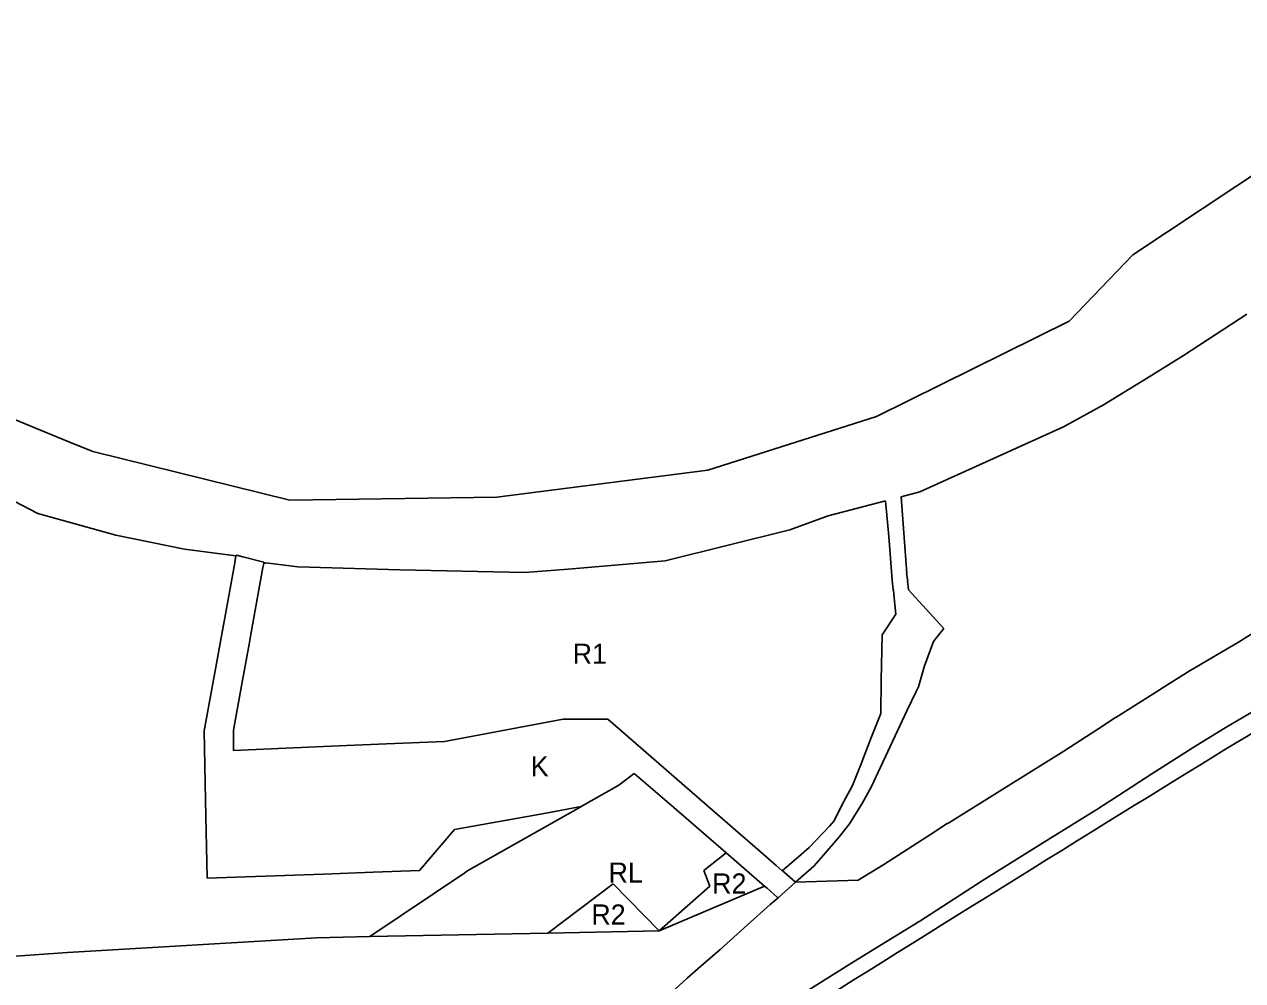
# Model space of a CAD drawing. Extents: x 7413438 to 7416393, y 5541665 to 5544118.
# Drawn here: x 7415261.6 to 7415625.7, y 5543211 to 5543496.8 of the extents above; entities that cross this region are included whole.
import ezdxf

# ---------------------------------------------------------------- set-up
doc = ezdxf.new("R2010")
doc.units = 0
for name, color, linetype in [('linie_rozgraniczajace', 7, 'Continuous'), ('linie_zabudowy_nieprzekraczalne', 7, 'Continuous'), ('oznaczenia_przeznaczen', 7, 'Continuous')]:
    doc.layers.add(name, color=color, linetype=linetype)

msp = doc.modelspace()

# ---------------------------------------------------------------- linework, layer by layer
at = {"layer": 'linie_rozgraniczajace'}
for p, q in [((7415592.88, 5543427.88), (7415696.54, 5543496.79)), ((7415573.83, 5543408.05), (7415592.88, 5543427.88)), ((7415626.92, 5543410.15), (7415608.04, 5543397.87)), ((7415516.21, 5543379.59), (7415573.83, 5543408.05)), ((7415608.04, 5543397.87), (7415596.16, 5543390.5)), ((7415231.77, 5543389.62), (7415274.89, 5543372.05)), ((7415591.51, 5543387.62), (7415584.28, 5543383.14)), ((7415596.16, 5543390.5), (7415591.51, 5543387.62)), ((7415584.28, 5543383.14), (7415572.1, 5543376.55)), ((7415465.82, 5543363.51), (7415516.21, 5543379.59)), ((7415572.1, 5543376.55), (7415529.2, 5543357.07)), ((7415274.89, 5543372.05), (7415282.08, 5543369.12)), ((7415282.08, 5543369.12), (7415340.86, 5543354.54)), ((7415402.82, 5543355.53), (7415465.82, 5543363.51)), ((7415265.57, 5543350.61), (7415253.67, 5543356.74)), ((7415340.86, 5543354.54), (7415402.82, 5543355.53)), ((7415529.2, 5543357.07), (7415523.58, 5543355.59)), ((7415523.58, 5543355.59), (7415525.28, 5543332.71)), ((7415518.92, 5543354.37), (7415501.79, 5543349.87)), ((7415519.95, 5543343.71), (7415518.92, 5543354.37)), ((7415288.87, 5543344.14), (7415265.57, 5543350.61)), ((7415501.79, 5543349.87), (7415490.31, 5543345.69)), ((7415309.43, 5543339.94), (7415288.87, 5543344.14)), ((7415490.31, 5543345.69), (7415453.09, 5543336.5)), ((7415520.89, 5543330.71), (7415519.95, 5543343.71)), ((7415324.81, 5543337.93), (7415309.43, 5543339.94)), ((7415324.48, 5543335.85), (7415324.81, 5543337.93)), ((7415324.85, 5543337.92), (7415324.81, 5543337.93)), ((7415324.9, 5543338.15), (7415324.85, 5543337.92)), ((7415325.01, 5543338.12), (7415324.9, 5543338.15)), ((7415326.84, 5543337.65), (7415325.01, 5543338.12)), ((7415333.18, 5543336.04), (7415326.84, 5543337.65)), ((7415453.09, 5543336.5), (7415424.06, 5543334)), ((7415321.07, 5543317.24), (7415324.48, 5543335.85)), ((7415332.88, 5543334.42), (7415329.35, 5543315.04)), ((7415333.13, 5543335.66), (7415332.88, 5543334.42)), ((7415333.11, 5543335.65), (7415333.18, 5543336.04)), ((7415333.13, 5543335.66), (7415333.11, 5543335.65)), ((7415333.69, 5543335.89), (7415333.13, 5543335.66)), ((7415343.27, 5543334.69), (7415333.69, 5543335.89)), ((7415373.76, 5543333.81), (7415343.27, 5543334.69)), ((7415411.13, 5543332.95), (7415373.76, 5543333.81)), ((7415424.06, 5543334), (7415411.13, 5543332.95)), ((7415525.28, 5543332.71), (7415525.23, 5543332.68)), ((7415525.23, 5543332.68), (7415525.57, 5543330.36)), ((7415520.93, 5543330.73), (7415520.89, 5543330.71)), ((7415521.22, 5543327.69), (7415520.93, 5543330.73)), ((7415525.57, 5543330.36), (7415525.52, 5543330.33)), ((7415525.52, 5543330.33), (7415525.8, 5543327.81)), ((7415521.3, 5543327.74), (7415521.22, 5543327.69)), ((7415521.42, 5543326.36), (7415521.3, 5543327.74)), ((7415522.04, 5543320.53), (7415521.42, 5543326.36)), ((7415525.8, 5543327.81), (7415536.39, 5543316.28)), ((7415517.9, 5543314.35), (7415522.04, 5543320.53)), ((7415320.37, 5543313.41), (7415320.98, 5543316.75)), ((7415320.98, 5543316.75), (7415321.03, 5543317)), ((7415321.03, 5543317), (7415321.07, 5543317.24)), ((7415329.34, 5543315), (7415328.71, 5543311.53)), ((7415329.35, 5543315.04), (7415329.34, 5543315)), ((7415536.39, 5543316.28), (7415534.33, 5543313.71)), ((7415633.26, 5543317.76), (7415624.41, 5543312.15)), ((7415318.77, 5543304.69), (7415320.37, 5543313.41)), ((7415328.71, 5543311.53), (7415326.45, 5543299.13)), ((7415517.62, 5543300.82), (7415517.9, 5543314.35)), ((7415533.3, 5543312.37), (7415530.61, 5543305.07)), ((7415534.33, 5543313.71), (7415533.3, 5543312.37)), ((7415624.41, 5543312.15), (7415610.19, 5543303.74)), ((7415315.3, 5543285.69), (7415318.77, 5543304.69)), ((7415530.61, 5543305.07), (7415528.76, 5543298.82)), ((7415610.01, 5543303.63), (7415601.1, 5543298.11)), ((7415610.19, 5543303.74), (7415610.01, 5543303.63)), ((7415517.52, 5543290.82), (7415517.62, 5543300.82)), ((7415326.45, 5543299.13), (7415324.03, 5543285.83)), ((7415528.12, 5543297.43), (7415525.36, 5543291.78)), ((7415528.76, 5543298.82), (7415528.12, 5543297.43)), ((7415601.01, 5543298.05), (7415587.77, 5543289.65)), ((7415601.02, 5543298.06), (7415601.01, 5543298.05)), ((7415601.1, 5543298.11), (7415601.02, 5543298.06)), ((7415620.46, 5543286.58), (7415634.72, 5543295.01)), ((7415387.11, 5543282.49), (7415422.61, 5543289.16)), ((7415422.61, 5543289.16), (7415435.94, 5543289.13)), ((7415435.94, 5543289.13), (7415443.47, 5543282.57)), ((7415514.58, 5543283.36), (7415517.52, 5543290.82)), ((7415525.36, 5543291.78), (7415517.47, 5543274.82)), ((7415587.68, 5543289.6), (7415582.43, 5543286.19)), ((7415587.77, 5543289.65), (7415587.68, 5543289.6)), ((7415315.74, 5543264.96), (7415315.3, 5543285.69)), ((7415324.03, 5543285.83), (7415324.1, 5543279.78)), ((7415582.43, 5543286.19), (7415572.2, 5543279.56)), ((7415611.68, 5543281.14), (7415620.46, 5543286.58)), ((7415353.24, 5543281.03), (7415369.82, 5543281.75)), ((7415369.82, 5543281.75), (7415387.11, 5543282.49)), ((7415443.47, 5543282.57), (7415465.75, 5543263.2)), ((7415511.7, 5543275.79), (7415514.58, 5543283.36)), ((7415324.1, 5543279.78), (7415353.24, 5543281.03)), ((7415572.2, 5543279.56), (7415555.59, 5543269.21)), ((7415598.52, 5543272.79), (7415611.68, 5543281.14)), ((7415509.1, 5543269.26), (7415511.7, 5543275.79)), ((7415517.47, 5543274.82), (7415514.71, 5543268.98)), ((7415443.84, 5543272.94), (7415439.21, 5543269.37)), ((7415455.65, 5543262.72), (7415443.84, 5543272.94)), ((7415586.61, 5543265.07), (7415598.52, 5543272.79)), ((7415439.21, 5543269.37), (7415427.97, 5543263)), ((7415505.78, 5543263.24), (7415509.1, 5543269.26)), ((7415514.71, 5543268.98), (7415512.05, 5543264.16)), ((7415555.59, 5543269.21), (7415537.54, 5543258)), ((7415316.24, 5543241.6), (7415315.74, 5543264.96)), ((7415512.05, 5543264.16), (7415508.17, 5543257.86)), ((7415583, 5543262.73), (7415586.61, 5543265.07)), ((7415416.96, 5543260.99), (7415390.16, 5543256.15)), ((7415427.91, 5543262.97), (7415393.84, 5543243.68)), ((7415426.36, 5543262.69), (7415416.96, 5543260.99)), ((7415427.97, 5543263), (7415426.36, 5543262.69)), ((7415427.97, 5543263), (7415427.91, 5543262.97)), ((7415471.17, 5543249.29), (7415455.65, 5543262.72)), ((7415465.75, 5543263.2), (7415481.49, 5543249.55)), ((7415503.61, 5543258.7), (7415505.78, 5543263.24)), ((7415566.16, 5543252.24), (7415582.85, 5543262.64)), ((7415582.85, 5543262.64), (7415582.91, 5543262.67)), ((7415582.91, 5543262.67), (7415583, 5543262.73)), ((7415390.16, 5543256.15), (7415379.69, 5543243.87)), ((7415496.11, 5543250.76), (7415502.15, 5543257.11)), ((7415502.15, 5543257.11), (7415503.61, 5543258.7)), ((7415508.17, 5543257.86), (7415505.14, 5543254.05)), ((7415537.39, 5543257.91), (7415532.69, 5543254.87)), ((7415537.47, 5543257.95), (7415537.39, 5543257.91)), ((7415537.54, 5543258), (7415537.47, 5543257.95)), ((7415505.14, 5543254.05), (7415499.73, 5543247.72)), ((7415532.69, 5543254.87), (7415518.44, 5543245.68)), ((7415464.62, 5543243.92), (7415471.32, 5543249.16)), ((7415471.32, 5543249.16), (7415471.17, 5543249.29)), ((7415482, 5543239.91), (7415471.32, 5543249.16)), ((7415481.49, 5543249.55), (7415486.28, 5543245.39)), ((7415492.91, 5543248.02), (7415496.11, 5543250.76)), ((7415548.17, 5543241.06), (7415566.15, 5543252.23)), ((7415566.15, 5543252.23), (7415566.16, 5543252.24)), ((7415486.28, 5543245.39), (7415488.05, 5543243.85)), ((7415488.17, 5543243.95), (7415492.91, 5543248.02)), ((7415499.73, 5543247.72), (7415497.48, 5543245.21)), ((7415518.44, 5543245.68), (7415510.81, 5543240.99)), ((7415350.98, 5543242.84), (7415316.24, 5543241.6)), ((7415365.82, 5543243.38), (7415350.98, 5543242.84)), ((7415393.21, 5543243.25), (7415364.86, 5543224.14)), ((7415379.69, 5543243.87), (7415365.82, 5543243.38)), ((7415393.84, 5543243.68), (7415393.21, 5543243.25)), ((7415466.4, 5543239.22), (7415464.62, 5543243.92)), ((7415488.05, 5543243.85), (7415488.17, 5543243.95)), ((7415488.14, 5543243.77), (7415488.17, 5543243.95)), ((7415488.7, 5543243.29), (7415488.14, 5543243.77)), ((7415492.04, 5543240.39), (7415488.7, 5543243.29)), ((7415497.48, 5543245.21), (7415492.04, 5543240.39)), ((7415418.06, 5543225.22), (7415437.51, 5543239.91)), ((7415437.51, 5543239.91), (7415451.32, 5543225.9)), ((7415451.32, 5543225.9), (7415466.4, 5543239.22)), ((7415451.32, 5543225.9), (7415482.79, 5543239.21)), ((7415482.8, 5543239.22), (7415482, 5543239.91)), ((7415482.79, 5543239.21), (7415482.8, 5543239.22)), ((7415482.8, 5543239.22), (7415482.8, 5543239.22)), ((7415482.8, 5543239.22), (7415483.52, 5543238.59)), ((7415483.52, 5543238.59), (7415486.67, 5543235.87)), ((7415492.06, 5543240.37), (7415486.81, 5543235.75)), ((7415510.81, 5543240.99), (7415492.04, 5543240.39)), ((7415492.04, 5543240.39), (7415492.06, 5543240.37)), ((7415529.19, 5543228.81), (7415548.17, 5543241.06)), ((7415486.81, 5543235.75), (7415484.43, 5543233.77)), ((7415486.67, 5543235.87), (7415486.81, 5543235.75)), ((7415484.43, 5543233.77), (7415477.55, 5543227.54)), ((7415477.55, 5543227.54), (7415469.49, 5543220.3)), ((7415509.39, 5543216.65), (7415529, 5543228.69)), ((7415529, 5543228.69), (7415529.07, 5543228.73)), ((7415529.07, 5543228.73), (7415529.12, 5543228.76)), ((7415529.12, 5543228.76), (7415529.19, 5543228.81)), ((7415274.51, 5543219.39), (7415348.9, 5543223.81)), ((7415348.9, 5543223.81), (7415364.86, 5543224.14)), ((7415364.86, 5543224.14), (7415418.06, 5543225.22)), ((7415418.06, 5543225.22), (7415451.32, 5543225.9)), ((7415469.49, 5543220.3), (7415462.95, 5543214.57)), ((7415245.72, 5543217.41), (7415274.51, 5543219.39)), ((7415491.71, 5543205.57), (7415509.39, 5543216.65)), ((7415462.95, 5543214.57), (7415459.66, 5543211.68)), ((7415462.95, 5543214.57), (7415462.95, 5543214.57)), ((7415459.66, 5543211.68), (7415451.33, 5543204.06))]:
    msp.add_line(p, q, dxfattribs=at)
at = {"layer": 'linie_zabudowy_nieprzekraczalne'}
msp.add_open_spline([(7415657.6, 5543302.19), (7415645.23, 5543296.35), (7415476.29, 5543190.53), (7415443.93, 5543170.24)], degree=3, dxfattribs=at)

# ---------------------------------------------------------------- texts
at = {"layer": 'oznaczenia_przeznaczen'}
for s, p in [('R1', (7415425.43, 5543305.71)), ('K', (7415412.91, 5543272.07)), ('RL', (7415436.15, 5543240.28)), ('R2', (7415467.11, 5543237.03)), ('R2', (7415431.01, 5543227.76))]:
    msp.add_text(s, height=6, dxfattribs=at).set_placement(p)

doc.saveas('drawing.dxf')
